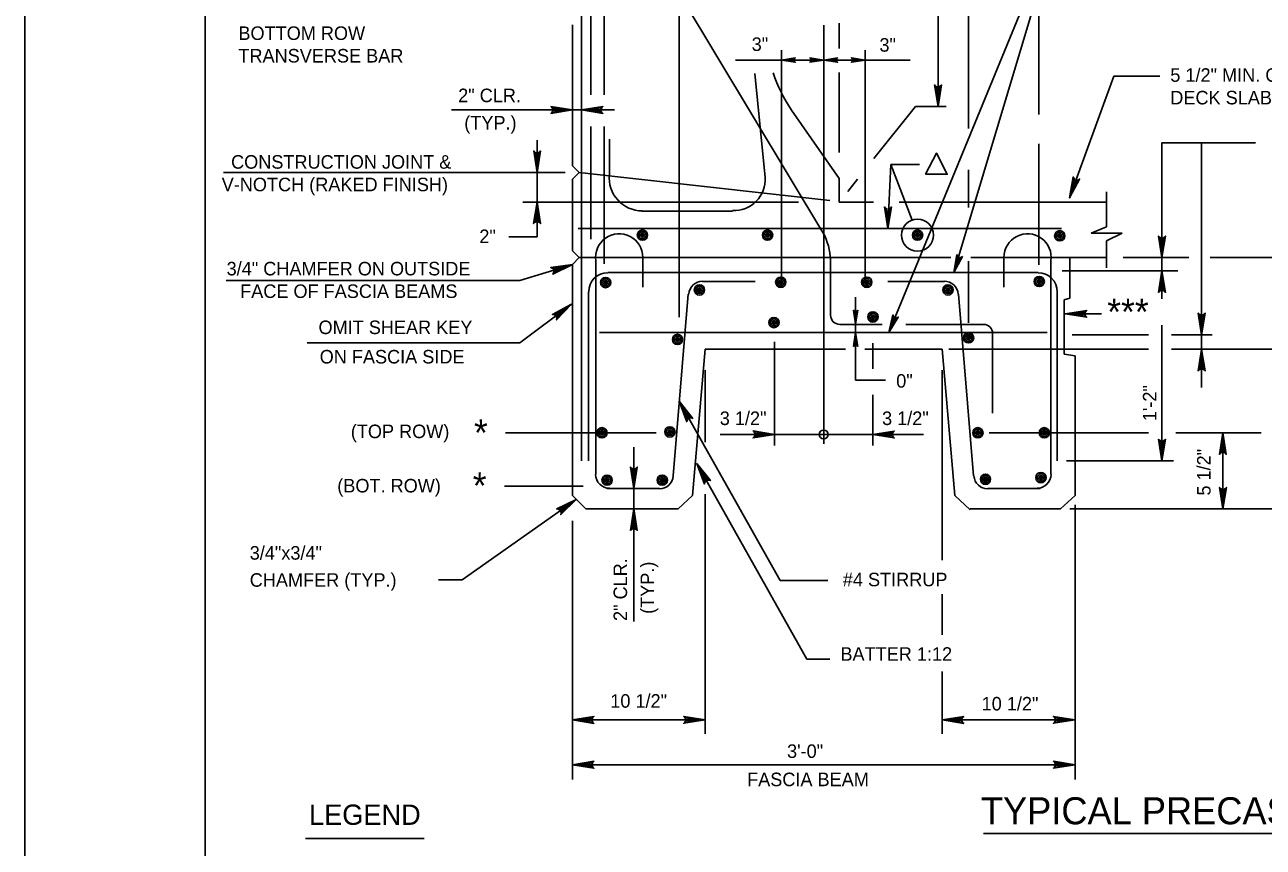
# Model space of a CAD drawing. Extents: x 642009 to 642864, y 298232 to 300014.
# Drawn here: x 642008.7 to 642283.1, y 299723.7 to 299906 of the extents above; entities that cross this region are included whole.
import ezdxf

# ---------------------------------------------------------------- set-up
doc = ezdxf.new("R2010")
doc.units = 0
for name, color, linetype in [('1', 7, 'Continuous'), ('2', 7, 'Continuous'), ('PLT-BNDY', 7, 'Continuous')]:
    doc.layers.add(name, color=color, linetype=linetype)

msp = doc.modelspace()

# ---------------------------------------------------------------- linework, layer by layer
at = {"layer": '1'}
for p, q in [((642200.54, 299875.06), (642199.93, 299860.85)), ((642200.54, 299875.06), (642205.28, 299862.73)), ((642187.07, 299867.07), (642131.52, 299873.27))]:
    msp.add_line(p, q, dxfattribs=at)
for points in [[(642211.61, 299892.44), (642211.28, 299892.27), (642211.04, 299887.9), (642211.61, 299892.44), (642211.81, 299892.67), (642211.04, 299887.9), (642210.83, 299892.27), (642210.5, 299892.43), (642211.04, 299887.9), (642210.28, 299892.67), (642210.5, 299892.43)], [(642125.47, 299887.69), (642125.64, 299887.36), (642130.01, 299887.12), (642125.47, 299887.69), (642125.24, 299887.89), (642130.01, 299887.12), (642125.65, 299886.9), (642125.49, 299886.58), (642130.01, 299887.12), (642125.24, 299886.36), (642125.49, 299886.58)], [(642136.54, 299886.55), (642136.37, 299886.88), (642132, 299887.12), (642136.54, 299886.55), (642136.77, 299886.35), (642132, 299887.12), (642136.37, 299887.33), (642136.53, 299887.66), (642132, 299887.12), (642136.77, 299887.88), (642136.53, 299887.66)], [(642122.76, 299877.81), (642122.43, 299877.64), (642122.19, 299873.27), (642122.76, 299877.81), (642122.96, 299878.04), (642122.19, 299873.27), (642121.97, 299877.64), (642121.65, 299877.8), (642122.19, 299873.27), (642121.43, 299878.04), (642121.65, 299877.8)], [(642121.62, 299862.18), (642121.95, 299862.35), (642122.19, 299866.72), (642121.62, 299862.18), (642121.42, 299861.94), (642122.19, 299866.72), (642122.41, 299862.35), (642122.73, 299862.19), (642122.19, 299866.72), (642122.95, 299861.94), (642122.73, 299862.19)], [(642200.5, 299865.39), (642200.17, 299865.22), (642199.93, 299860.85), (642200.5, 299865.39), (642200.7, 299865.63), (642199.93, 299860.85), (642199.72, 299865.22), (642199.39, 299865.38), (642199.93, 299860.85), (642199.17, 299865.63), (642199.39, 299865.38)], [(642261.22, 299858.93), (642260.89, 299858.76), (642260.65, 299854.39), (642261.22, 299858.93), (642261.42, 299859.16), (642260.65, 299854.39), (642260.44, 299858.76), (642260.11, 299858.91), (642260.65, 299854.39), (642259.89, 299859.16), (642260.11, 299858.91)], [(642125.83, 299851), (642125.9, 299851.37), (642130.01, 299852.86), (642125.83, 299851), (642125.67, 299850.75), (642130.01, 299852.86), (642125.77, 299851.81), (642125.52, 299852.07), (642130.01, 299852.86), (642125.22, 299852.21), (642125.52, 299852.07)], [(642260.08, 299846.93), (642260.41, 299847.09), (642260.65, 299851.47), (642260.08, 299846.93), (642259.88, 299846.69), (642260.65, 299851.47), (642260.87, 299847.1), (642261.19, 299846.94), (642260.65, 299851.47), (642261.41, 299846.69), (642261.19, 299846.94)], [(642126.55, 299840.89), (642126.49, 299841.26), (642129.84, 299844.07), (642126.55, 299840.89), (642126.49, 299840.59), (642129.84, 299844.07), (642126.22, 299841.63), (642125.9, 299841.79), (642129.84, 299844.07), (642125.57, 299841.82), (642125.9, 299841.79)], [(642243.76, 299841.38), (642243.59, 299841.71), (642239.22, 299841.95), (642243.76, 299841.38), (642243.99, 299841.18), (642239.22, 299841.95), (642243.59, 299842.16), (642243.75, 299842.49), (642239.22, 299841.95), (642243.99, 299842.71), (642243.75, 299842.49)], [(642270.02, 299841.87), (642269.69, 299841.7), (642269.45, 299837.32), (642270.02, 299841.87), (642270.22, 299842.1), (642269.45, 299837.32), (642269.24, 299841.69), (642268.91, 299841.85), (642269.45, 299837.32), (642268.69, 299842.1), (642268.91, 299841.85)], [(642268.88, 299829.51), (642269.21, 299829.68), (642269.45, 299834.05), (642268.88, 299829.51), (642268.68, 299829.28), (642269.45, 299834.05), (642269.67, 299829.68), (642269.99, 299829.52), (642269.45, 299834.05), (642270.21, 299829.28), (642269.99, 299829.52)], [(642155.42, 299818.33), (642155.62, 299818.64), (642153.68, 299822.57), (642155.42, 299818.33), (642155.36, 299818.03), (642153.68, 299822.57), (642156.02, 299818.87), (642156.38, 299818.89), (642153.68, 299822.57), (642156.69, 299818.78), (642156.38, 299818.89)], [(642170.29, 299815.78), (642170.45, 299815.45), (642174.83, 299815.21), (642170.29, 299815.78), (642170.05, 299815.98), (642174.83, 299815.21), (642170.46, 299814.99), (642170.3, 299814.67), (642174.83, 299815.21), (642170.05, 299814.45), (642170.3, 299814.67)], [(642201.12, 299814.64), (642200.95, 299814.97), (642196.58, 299815.21), (642201.12, 299814.64), (642201.35, 299814.44), (642196.58, 299815.21), (642200.94, 299815.42), (642201.1, 299815.75), (642196.58, 299815.21), (642201.35, 299815.97), (642201.1, 299815.75)], [(642261.22, 299813.93), (642260.89, 299813.76), (642260.65, 299809.39), (642261.22, 299813.93), (642261.42, 299814.16), (642260.65, 299809.39), (642260.44, 299813.76), (642260.11, 299813.91), (642260.65, 299809.39), (642259.89, 299814.16), (642260.11, 299813.91)], [(642273.59, 299811.03), (642273.92, 299811.2), (642274.17, 299815.57), (642273.59, 299811.03), (642273.4, 299810.8), (642274.17, 299815.57), (642274.38, 299811.21), (642274.71, 299811.05), (642274.17, 299815.57), (642274.92, 299810.8), (642274.71, 299811.05)], [(642144.2, 299807.74), (642143.87, 299807.57), (642143.63, 299803.2), (642144.2, 299807.74), (642144.4, 299807.97), (642143.63, 299803.2), (642143.42, 299807.57), (642143.09, 299807.73), (642143.63, 299803.2), (642142.87, 299807.97), (642143.09, 299807.73)], [(642159.31, 299804.52), (642159.51, 299804.83), (642157.58, 299808.76), (642159.31, 299804.52), (642159.25, 299804.22), (642157.58, 299808.76), (642159.91, 299805.06), (642160.27, 299805.08), (642157.58, 299808.76), (642160.58, 299804.97), (642160.27, 299805.08)], [(642274.73, 299803.24), (642274.41, 299803.07), (642274.17, 299798.7), (642274.73, 299803.24), (642274.93, 299803.47), (642274.17, 299798.7), (642273.95, 299803.07), (642273.62, 299803.23), (642274.17, 299798.7), (642273.41, 299803.47), (642273.62, 299803.23)], [(642126.84, 299798.68), (642127.17, 299798.51), (642130.88, 299800.83), (642126.84, 299798.68), (642126.54, 299798.71), (642130.88, 299800.83), (642127.44, 299798.13), (642127.5, 299797.78), (642130.88, 299800.83), (642127.42, 299797.46), (642127.5, 299797.78)], [(642143.06, 299794.16), (642143.39, 299794.33), (642143.63, 299798.7), (642143.06, 299794.16), (642142.86, 299793.93), (642143.63, 299798.7), (642143.85, 299794.33), (642144.17, 299794.17), (642143.63, 299798.7), (642144.39, 299793.93), (642144.17, 299794.17)], [(642134.55, 299751.38), (642134.39, 299751.71), (642130.01, 299751.95), (642134.55, 299751.38), (642134.79, 299751.18), (642130.01, 299751.95), (642134.38, 299752.17), (642134.54, 299752.49), (642130.01, 299751.95), (642134.79, 299752.71), (642134.54, 299752.49)], [(642154.91, 299752.52), (642155.08, 299752.19), (642159.45, 299751.95), (642154.91, 299752.52), (642154.68, 299752.72), (642159.45, 299751.95), (642155.08, 299751.74), (642154.92, 299751.41), (642159.45, 299751.95), (642154.68, 299751.19), (642154.92, 299751.41)], [(642216.49, 299751.38), (642216.32, 299751.71), (642211.95, 299751.95), (642216.49, 299751.38), (642216.72, 299751.18), (642211.95, 299751.95), (642216.32, 299752.17), (642216.48, 299752.49), (642211.95, 299751.95), (642216.72, 299752.71), (642216.48, 299752.49)], [(642236.85, 299752.52), (642237.02, 299752.19), (642241.39, 299751.95), (642236.85, 299752.52), (642236.61, 299752.72), (642241.39, 299751.95), (642237.02, 299751.74), (642236.86, 299751.41), (642241.39, 299751.95), (642236.61, 299751.19), (642236.86, 299751.41)], [(642134.55, 299741.45), (642134.39, 299741.78), (642130.01, 299742.02), (642134.55, 299741.45), (642134.79, 299741.25), (642130.01, 299742.02), (642134.38, 299742.24), (642134.54, 299742.57), (642130.01, 299742.02), (642134.79, 299742.78), (642134.54, 299742.57)], [(642236.85, 299742.59), (642237.02, 299742.27), (642241.39, 299742.02), (642236.85, 299742.59), (642236.61, 299742.79), (642241.39, 299742.02), (642237.02, 299741.81), (642236.86, 299741.48), (642241.39, 299742.02), (642236.61, 299741.27), (642236.86, 299741.48)]]:
    msp.add_lwpolyline(points, dxfattribs=at)
msp.add_lwpolyline([(642208.26, 299872.88), (642210.67, 299877.57), (642213.08, 299872.88)], close=True, dxfattribs=at)
for centre, radius in [((642206.49, 299859.39), 3.55), ((642185.7, 299815.21), 0.983)]:
    msp.add_circle(centre, radius, dxfattribs=at)
at = {"layer": '2'}
for p, q in [((642048.66, 299434.82), (642048.66, 299998.82)), ((642137.05, 299951.04), (642137.05, 299890.47)), ((642153.64, 299939.21), (642153.64, 299841.18)), ((642217.76, 299939.21), (642217.76, 299883.05)), ((642238.62, 299931.48), (642200.14, 299837.77)), ((642211.04, 299887.9), (642211.04, 299932.15)), ((642238.62, 299931.48), (642214.57, 299851.07)), ((642134.1, 299918.05), (642134.1, 299890.47)), ((642152.58, 299914.82), (642185.93, 299859.22)), ((642132, 299809.39), (642132, 299910.7)), ((642233.39, 299910.03), (642233.39, 299886.15)), ((642130.01, 299906), (642130.01, 299874.77)), ((642185.7, 299813.15), (642185.7, 299905.9)), ((642189.13, 299900.73), (642189.13, 299906.36)), ((642176.33, 299848.97), (642176.33, 299900.4)), ((642194.89, 299848.67), (642194.89, 299900.4)), ((642176.33, 299898.18), (642166.13, 299898.18)), ((642194.89, 299898.18), (642176.33, 299898.18)), ((642204.88, 299898.18), (642194.89, 299898.18)), ((642172.74, 299872.16), (642170.41, 299895.24)), ((642189.13, 299877.69), (642189.13, 299895.4)), ((642240.18, 299867.63), (642250, 299894.65)), ((642250, 299894.65), (642260.2, 299894.65)), ((642206.02, 299887.9), (642196.84, 299876.38)), ((642212.81, 299887.9), (642206.02, 299887.9)), ((642132, 299887.12), (642103.24, 299887.12)), ((642139.33, 299887.12), (642132, 299887.12)), ((642189.13, 299871.94), (642178.6, 299887.07)), ((642134.1, 299883.49), (642134.1, 299858.5)), ((642137.05, 299883.49), (642137.05, 299853.03)), ((642122.19, 299880.41), (642122.19, 299858.97)), ((642138.2, 299872.82), (642138.2, 299880.63)), ((642233.39, 299879.64), (642233.39, 299852.78)), ((642260.65, 299879.87), (642260.65, 299854.39)), ((642281.36, 299879.87), (642260.65, 299879.87)), ((642269.45, 299879.87), (642269.45, 299837.32)), ((642130.01, 299874.77), (642131.52, 299873.27)), ((642206.91, 299875.06), (642200.54, 299875.06)), ((642217.76, 299873.82), (642217.76, 299865.52)), ((642128.44, 299873.27), (642052.69, 299873.27)), ((642131.52, 299873.27), (642130.01, 299871.76)), ((642130.01, 299871.76), (642130.01, 299855.91)), ((642189.13, 299871.94), (642189.13, 299866.72)), ((642193.18, 299871.79), (642191.02, 299869.09)), ((642248.34, 299868.96), (642248.34, 299861.21)), ((642180.11, 299866.72), (642119.04, 299866.72)), ((642196.75, 299866.72), (642189.13, 299866.72)), ((642248.34, 299866.72), (642202.43, 299866.72)), ((642165.49, 299864.73), (642145.39, 299864.73)), ((642238.38, 299860.85), (642131.26, 299860.85)), ((642244.97, 299859.81), (642248.34, 299861.21)), ((642122.19, 299858.97), (642115.96, 299858.97)), ((642244.97, 299859.81), (642251.84, 299859.81)), ((642248.34, 299858.14), (642251.84, 299859.81)), ((642248.34, 299858.14), (642248.34, 299852.11)), ((642130.01, 299855.91), (642131.54, 299854.39)), ((642130.01, 299852.86), (642118.39, 299849.32)), ((642130.01, 299852.86), (642131.54, 299854.39)), ((642130.01, 299852.86), (642130.01, 299801.7)), ((642213.87, 299854.39), (642131.54, 299854.39)), ((642135.22, 299853.69), (642135.22, 299806.37)), ((642145.62, 299854.45), (642145.62, 299847.88)), ((642187.24, 299841.61), (642187.24, 299853.1)), ((642217.76, 299853.64), (642217.76, 299839.96)), ((642248.34, 299854.39), (642218.27, 299854.39)), ((642225.65, 299854.45), (642225.65, 299847.88)), ((642236.05, 299853.69), (642236.05, 299806.39)), ((642240.26, 299854.39), (642240.26, 299845.39)), ((642266.61, 299854.39), (642252.03, 299854.39)), ((642260.65, 299854.39), (642260.65, 299845.27)), ((642372.27, 299854.39), (642271.33, 299854.39)), ((642118.39, 299849.32), (642053.31, 299849.32)), ((642233.21, 299851.07), (642137.87, 299851.07)), ((642170.49, 299849.11), (642158.87, 299849.11)), ((642199.89, 299849.11), (642212.46, 299849.11)), ((642264.14, 299851.47), (642238.54, 299851.47)), ((642133.61, 299846.81), (642133.61, 299809.39)), ((642155.63, 299846.33), (642152.33, 299806.01)), ((642215.58, 299846.33), (642218.89, 299806.01)), ((642237.46, 299846.81), (642237.46, 299809.39)), ((642129.84, 299844.07), (642118.39, 299835.48)), ((642192.78, 299836.78), (642192.78, 299845.65)), ((642240.26, 299845.39), (642238.95, 299845.01)), ((642238.95, 299845.01), (642238.95, 299833.01)), ((642239.22, 299841.95), (642247.29, 299841.95)), ((642189.24, 299839.61), (642198.63, 299839.61)), ((642203.89, 299839.61), (642221.13, 299839.61)), ((642260.65, 299839.46), (642260.65, 299809.39)), ((642118.39, 299835.48), (642071.25, 299835.48)), ((642235.2, 299837.77), (642136.01, 299837.77)), ((642174.83, 299812.77), (642174.83, 299835.76)), ((642192.78, 299827.23), (642192.78, 299836.78)), ((642196.58, 299829.76), (642196.58, 299835.46)), ((642223.13, 299837.61), (642223.13, 299819.91)), ((642257.64, 299837.32), (642240.78, 299837.32)), ((642271.77, 299837.32), (642262.8, 299837.32)), ((642269.45, 299837.14), (642269.45, 299825.63)), ((642159.45, 299834.14), (642156.64, 299801.7)), ((642190.56, 299834.14), (642159.45, 299834.14)), ((642211.95, 299834.14), (642194.79, 299834.14)), ((642211.95, 299834.14), (642214.76, 299801.7)), ((642257.64, 299834.14), (642213.43, 299834.14)), ((642238.95, 299833.01), (642241.39, 299832.64)), ((642241.39, 299832.64), (642241.39, 299801.7)), ((642298.81, 299834.14), (642262.8, 299834.14)), ((642159.45, 299829.45), (642159.45, 299813.51)), ((642199.42, 299827.23), (642192.78, 299827.23)), ((642211.95, 299829.45), (642211.95, 299787.37)), ((642176.06, 299782.86), (642153.68, 299822.57)), ((642196.58, 299812.77), (642196.58, 299823.97)), ((642148.58, 299815.57), (642115.2, 299815.57)), ((642174.83, 299815.21), (642162.77, 299815.21)), ((642185.7, 299815.21), (642174.83, 299815.21)), ((642196.58, 299815.21), (642185.7, 299815.21)), ((642207.85, 299815.21), (642196.58, 299815.21)), ((642243.26, 299815.57), (642222.34, 299815.57)), ((642257.64, 299815.57), (642242.14, 299815.57)), ((642282.65, 299815.57), (642263.7, 299815.57)), ((642274.17, 299815.57), (642274.17, 299798.7)), ((642143.63, 299812.4), (642143.63, 299803.2)), ((642181.99, 299765.44), (642157.58, 299808.76)), ((642263.25, 299809.39), (642239.49, 299809.39)), ((642274.17, 299805.64), (642274.17, 299798.7)), ((642132.43, 299803.76), (642114.98, 299803.76)), ((642137.7, 299803.2), (642149.33, 299803.2)), ((642143.63, 299803.2), (642143.63, 299798.7)), ((642233.7, 299803.2), (642222.08, 299803.2)), ((642130.88, 299800.83), (642105.6, 299782.97)), ((642130.01, 299801.7), (642133.01, 299798.7)), ((642156.64, 299801.7), (642153.46, 299798.7)), ((642159.45, 299801.96), (642159.45, 299748.83)), ((642214.76, 299801.7), (642218.14, 299798.51)), ((642241.39, 299801.7), (642238.2, 299798.7)), ((642241.39, 299738.72), (642241.39, 299799.64)), ((642133.01, 299798.7), (642153.46, 299798.7)), ((642143.63, 299798.7), (642143.63, 299773.76)), ((642238.2, 299798.7), (642218.14, 299798.7)), ((642387.3, 299798.7), (642240.26, 299798.7)), ((642274.17, 299798.7), (642274.17, 299798.7)), ((642130.01, 299738.72), (642130.01, 299796.1)), ((642105.6, 299782.97), (642100.31, 299782.97)), ((642186.64, 299782.86), (642176.06, 299782.86)), ((642211.95, 299779.8), (642211.95, 299770.82)), ((642187.07, 299765.44), (642181.99, 299765.44)), ((642211.95, 299762.65), (642211.95, 299748.83)), ((642159.45, 299751.95), (642130.01, 299751.95)), ((642241.39, 299751.95), (642211.95, 299751.95)), ((642241.39, 299742.02), (642130.01, 299742.02)), ((642070.86, 299725.63), (642097.13, 299725.63)), ((642221.12, 299726.76), (642408.84, 299726.76))]:
    msp.add_line(p, q, dxfattribs=at)
for points in [[(642179.23, 299897.82), (642179.12, 299898.03), (642176.33, 299898.18), (642179.23, 299897.82), (642179.38, 299897.69), (642176.33, 299898.18), (642179.12, 299898.32), (642179.22, 299898.53), (642176.33, 299898.18), (642179.38, 299898.67), (642179.22, 299898.53)], [(642182.79, 299898.55), (642182.9, 299898.34), (642185.7, 299898.18), (642182.79, 299898.55), (642182.65, 299898.68), (642185.7, 299898.18), (642182.9, 299898.05), (642182.8, 299897.84), (642185.7, 299898.18), (642182.65, 299897.7), (642182.8, 299897.84)], [(642188.61, 299897.82), (642188.5, 299898.03), (642185.7, 299898.18), (642188.61, 299897.82), (642188.76, 299897.69), (642185.7, 299898.18), (642188.5, 299898.32), (642188.6, 299898.53), (642185.7, 299898.18), (642188.76, 299898.67), (642188.6, 299898.53)], [(642191.98, 299898.55), (642192.09, 299898.34), (642194.89, 299898.18), (642191.98, 299898.55), (642191.83, 299898.68), (642194.89, 299898.18), (642192.09, 299898.05), (642191.99, 299897.84), (642194.89, 299898.18), (642191.83, 299897.7), (642191.99, 299897.84)], [(642242.15, 299871.65), (642241.79, 299871.6), (642240.18, 299867.63), (642242.15, 299871.65), (642242.41, 299871.8), (642240.18, 299867.63), (642241.37, 299871.74), (642241.12, 299871.99), (642240.18, 299867.63), (642240.99, 299872.29), (642241.12, 299871.99)], [(642216.21, 299854.5), (642215.9, 299854.46), (642214.57, 299851.07), (642216.21, 299854.5), (642216.43, 299854.64), (642214.57, 299851.07), (642215.54, 299854.57), (642215.33, 299854.79), (642214.57, 299851.07), (642215.22, 299855.04), (642215.33, 299854.79)], [(642193.12, 299842.6), (642192.91, 299842.49), (642192.75, 299839.7), (642193.12, 299842.6), (642193.25, 299842.75), (642192.75, 299839.7), (642192.62, 299842.49), (642192.41, 299842.59), (642192.75, 299839.7), (642192.27, 299842.75), (642192.41, 299842.59)], [(642202, 299841.09), (642201.7, 299841.06), (642200.14, 299837.77), (642202, 299841.09), (642202.23, 299841.21), (642200.14, 299837.77), (642201.34, 299841.2), (642201.14, 299841.43), (642200.14, 299837.77), (642201.05, 299841.69), (642201.14, 299841.43)], [(642192.41, 299834.86), (642192.62, 299834.97), (642192.78, 299837.77), (642192.41, 299834.86), (642192.29, 299834.71), (642192.78, 299837.77), (642192.92, 299834.97), (642193.13, 299834.87), (642192.78, 299837.77), (642193.26, 299834.71), (642193.13, 299834.87)]]:
    msp.add_lwpolyline(points, dxfattribs=at)
for centre, radius in [((642145.53, 299859.39), 1.14), ((642145.53, 299859.39), 0.817), ((642173.26, 299859.39), 1.14), ((642173.26, 299859.39), 0.817), ((642206.49, 299859.39), 1.14), ((642206.49, 299859.39), 0.817), ((642238.01, 299859.24), 1.14), ((642238.01, 299859.24), 0.817), ((642145.53, 299859.39), 0.447), ((642145.53, 299859.39), 0.225), ((642145.53, 299859.39), 0.0966), ((642173.26, 299859.39), 0.447), ((642173.26, 299859.39), 0.225), ((642173.26, 299859.39), 0.0966), ((642206.49, 299859.39), 0.447), ((642206.49, 299859.39), 0.225), ((642206.49, 299859.39), 0.0966), ((642238.01, 299859.24), 0.447), ((642238.01, 299859.24), 0.225), ((642238.01, 299859.24), 0.0966), ((642137.38, 299848.88), 1.14), ((642137.38, 299848.88), 0.817), ((642137.38, 299848.88), 0.447), ((642137.38, 299848.88), 0.225), ((642137.38, 299848.88), 0.0966), ((642176.18, 299848.93), 1.14), ((642176.18, 299848.93), 0.817), ((642176.18, 299848.93), 0.447), ((642176.18, 299848.93), 0.225), ((642176.18, 299848.93), 0.0966), ((642195.23, 299848.93), 1.14), ((642195.23, 299848.93), 0.817), ((642195.23, 299848.93), 0.447), ((642195.23, 299848.93), 0.225), ((642195.23, 299848.93), 0.0966), ((642233.46, 299849.11), 1.14), ((642233.46, 299849.11), 0.817), ((642233.46, 299849.11), 0.447), ((642233.46, 299849.11), 0.225), ((642233.46, 299849.11), 0.0966), ((642158.16, 299847.24), 1.14), ((642158.16, 299847.24), 0.817), ((642158.16, 299847.24), 0.447), ((642158.16, 299847.24), 0.225), ((642158.16, 299847.24), 0.0966), ((642213.24, 299847.24), 1.14), ((642213.24, 299847.24), 0.817), ((642213.24, 299847.24), 0.447), ((642213.24, 299847.24), 0.225), ((642213.24, 299847.24), 0.0966), ((642174.68, 299840.01), 1.14), ((642174.68, 299840.01), 0.817), ((642196.61, 299841.25), 1.14), ((642196.61, 299841.25), 0.817), ((642196.61, 299841.25), 0.447), ((642196.61, 299841.25), 0.225), ((642196.61, 299841.25), 0.0966), ((642174.68, 299840.01), 0.447), ((642174.68, 299840.01), 0.225), ((642174.68, 299840.01), 0.0966), ((642153.3, 299836.26), 1.14), ((642153.3, 299836.26), 0.817), ((642153.3, 299836.26), 0.447), ((642153.3, 299836.26), 0.225), ((642153.3, 299836.26), 0.0966), ((642217.8, 299836.64), 1.14), ((642217.8, 299836.64), 0.817), ((642217.8, 299836.64), 0.447), ((642217.8, 299836.64), 0.225), ((642217.8, 299836.64), 0.0966), ((642136.57, 299815.58), 1.14), ((642136.57, 299815.58), 0.817), ((642151.61, 299815.77), 1.14), ((642151.61, 299815.77), 0.817), ((642151.61, 299815.77), 0.447), ((642219.86, 299815.58), 1.14), ((642219.86, 299815.58), 0.817), ((642234.59, 299815.58), 1.14), ((642234.59, 299815.58), 0.817), ((642136.57, 299815.58), 0.447), ((642136.57, 299815.58), 0.225), ((642136.57, 299815.58), 0.0966), ((642151.61, 299815.77), 0.225), ((642151.61, 299815.77), 0.0966), ((642219.86, 299815.58), 0.447), ((642219.86, 299815.58), 0.225), ((642219.86, 299815.58), 0.0966), ((642234.59, 299815.58), 0.447), ((642234.59, 299815.58), 0.225), ((642234.59, 299815.58), 0.0966), ((642137.7, 299805.08), 1.14), ((642137.7, 299805.08), 0.817), ((642137.7, 299805.08), 0.447), ((642137.7, 299805.08), 0.225), ((642137.7, 299805.08), 0.0966), ((642149.93, 299805.08), 1.14), ((642149.93, 299805.08), 0.817), ((642149.93, 299805.08), 0.447), ((642149.93, 299805.08), 0.225), ((642149.93, 299805.08), 0.0966), ((642221.55, 299805.27), 1.14), ((642221.55, 299805.27), 0.817), ((642221.55, 299805.27), 0.447), ((642221.55, 299805.27), 0.225), ((642221.55, 299805.27), 0.0966), ((642233.84, 299805.64), 1.14), ((642233.84, 299805.64), 0.817), ((642233.84, 299805.64), 0.447), ((642233.84, 299805.64), 0.225), ((642233.84, 299805.64), 0.0966)]:
    msp.add_circle(centre, radius, dxfattribs=at)
for centre, radius, start, end in [((642203.99, 299904.75), 30.94, 197.7404, 214.8547), ((642145.48, 299872.07), 7.31, 174.1623, 270), ((642165.8, 299871.76), 6.95, 267.4341, 3.2718), ((642140.39, 299854.45), 5.23, 0, 188.3783), ((642172.24, 299853.1), 15, 360, 24.0756), ((642230.88, 299854.45), 5.23, 351.6217, 180), ((642137.87, 299846.81), 4.25, 90, 180), ((642158.86, 299846.06), 3.09, 90, 175.2381), ((642212.42, 299846.06), 3.09, 4.7619, 90), ((642233.21, 299846.81), 4.25, 0, 90), ((642189.24, 299841.61), 2, 180, 270), ((642221.13, 299837.61), 2, 0, 90), ((642138.24, 299806.37), 3.09, 180, 270), ((642149.29, 299806.25), 3.09, 270, 355.2392), ((642222.06, 299806.25), 3.09, 184.7608, 270), ((642232.98, 299806.37), 3.09, 270, 0)]:
    msp.add_arc(centre, radius, start, end, dxfattribs=at)
at = {"layer": 'PLT-BNDY'}
msp.add_lwpolyline([(642008.66, 300013.82), (642849.66, 300013.82), (642849.66, 299419.82), (642008.66, 299419.82)], close=True, dxfattribs=at)

# ---------------------------------------------------------------- texts
at = {"layer": '2'}
for s, height, p in [('BOTTOM ROW', 3, (642056, 299902.64)), ('3"', 3, (642169.74, 299900.2)), ('3"', 3, (642198.05, 299900.04)), ('TRANSVERSE BAR', 3, (642056, 299897.64)), ('5 1/2" MIN. COMPOSITE CONCRETE', 3, (642262.51, 299893.36)), ('2" CLR.', 3, (642104.7, 299888.85)), ('DECK SLAB THICKNESS "T"', 3, (642262.51, 299888.36)), ('(TYP.)', 3, (642106.05, 299882.79)), ('CONSTRUCTION JOINT &', 3, (642054.38, 299874.11)), ('V-NOTCH (RAKED FINISH)', 3, (642052.3, 299869.11)), ('2"', 3, (642109.39, 299857.62)), ('3/4" CHAMFER ON OUTSIDE', 3, (642053.39, 299850.46)), ('FACE OF FASCIA BEAMS', 3, (642056.39, 299845.46)), ('***', 5.88, (642248.53, 299839.44)), ('OMIT SHEAR KEY', 3, (642073.75, 299837.45)), ('ON FASCIA SIDE', 3, (642074.01, 299830.94)), ('0"', 3, (642201.77, 299825.58)), ('3 1/2"', 3, (642162.67, 299817.3)), ('3 1/2"', 3, (642198.63, 299817.3)), ('(TOP ROW)', 3, (642080.91, 299814.39)), ('*', 5.88, (642108.2, 299812.66)), ('(BOT. ROW)', 3, (642077.91, 299802.36)), ('*', 5.88, (642107.93, 299800.93)), ('3/4"x3/4"', 3, (642058.51, 299787.46)), ('CHAMFER (TYP.)', 3, (642058.51, 299781.46)), ('#4 STIRRUP', 3, (642189.94, 299781.56)), ('BATTER 1:12', 3, (642189.41, 299765.06)), ('10 1/2"', 3, (642138.41, 299754.65)), ('10 1/2"', 3, (642220.7, 299754.04)), ('3\'-0"', 3, (642177.58, 299743.52)), ('FASCIA BEAM', 3, (642168.73, 299737.26)), ('TYPICAL PRECAST CHANNEL SECTIONS', 6, (642220.53, 299728.81)), ('LEGEND', 4.5, (642071.65, 299728.69))]:
    msp.add_text(s, height=height, dxfattribs=at).set_placement(p)
for s, p in [('1\'-2"', (642259.43, 299818.15)), ('5 1/2"', (642271.44, 299801.66)), ('2" CLR.', (642142.13, 299773.87)), ('(TYP.)', (642148.13, 299775.44))]:
    msp.add_text(s, height=3, rotation=90, dxfattribs=at).set_placement(p)

doc.saveas('drawing.dxf')
